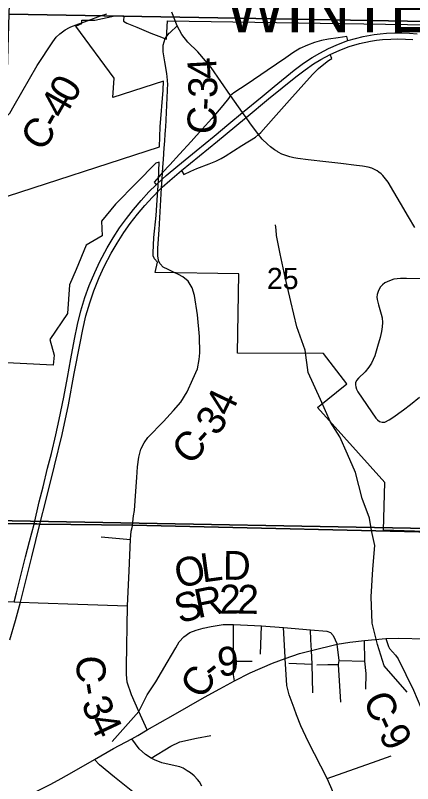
# Model space of a CAD drawing. Extents: x -19 to 40.8, y -1.8 to 26.1.
# Drawn here: x 5.34 to 6.121, y 15.443 to 16.956 of the extents above; entities that cross this region are included whole.
import ezdxf

# ---------------------------------------------------------------- set-up
doc = ezdxf.new("R2010")
doc.units = 0
for name, color, linetype in [('GM_X_City_Street', 7, 'Continuous'), ('GM_X_Corporation', 7, 'Continuous'), ('GM_X_County_Road', 7, 'Continuous'), ('GM_X_County_Road_Text', 7, 'Continuous'), ('GM_X_Major_River_Text', 7, 'Continuous'), ('GM_X_Rail_Line', 7, 'Continuous'), ('GM_X_Rail_Line_Text', 7, 'Continuous'), ('GM_X_Section', 7, 'Continuous'), ('GM_X_Section_Text', 7, 'Continuous'), ('GM_X_State_Route', 7, 'Continuous'), ('GM_X_Township_Road', 7, 'Continuous'), ('RW_P_Text', 7, 'Continuous')]:
    doc.layers.add(name, color=color, linetype=linetype)

msp = doc.modelspace()

# ---------------------------------------------------------------- linework, layer by layer
at = {"layer": 'GM_X_City_Street'}
for points in [[(5.2997, 16.5919), (5.6233, 16.6968), (5.6245, 16.736), (5.6304, 16.8084), (5.6314, 16.8263), (5.5318, 16.794), (5.5338, 16.8318), (5.4585, 16.9344), (5.4705, 16.9399), (5.4705, 16.9461), (5.4959, 16.9461), (5.5354, 16.9549), (5.5531, 16.9549), (5.5527, 16.944), (5.5593, 16.9404), (5.5785, 16.9328), (5.6064, 16.9208), (5.6217, 16.9151), (5.6372, 16.9092), (5.6373, 16.9102), (5.6389, 16.9451), (6.325, 16.9348)], [(6.2469, 15.9361), (6.0635, 15.9423), (6.0667, 16.0361), (5.9343, 16.1836), (5.9917, 16.2304), (5.946, 16.2903), (5.7766, 16.2907), (5.7795, 16.4467), (5.6145, 16.4497), (5.6191, 16.4696), (5.6133, 16.4766), (5.6111, 16.482), (5.6105, 16.4881), (5.6123, 16.5184), (5.6169, 16.5618), (5.6182, 16.5823), (5.6212, 16.6305), (5.6223, 16.6668), (5.6161, 16.665), (5.5781, 16.6258), (5.5365, 16.5843), (5.509, 16.5503), (5.5105, 16.5217), (5.4792, 16.503), (5.4591, 16.4556), (5.4462, 16.4254), (5.4423, 16.3689), (5.4076, 16.3176), (5.4159, 16.2869), (5.4141, 16.267), (5.2834, 16.2739)]]:
    msp.add_lwpolyline(points, dxfattribs=at)
at = {"layer": 'GM_X_Corporation'}
for p, q in [((5.644, 16.9219), (5.6582, 16.9352)), ((5.633, 16.7003), (5.6352, 16.7304))]:
    msp.add_line(p, q, dxfattribs=at)
for points in [[(5.483, 16.9459), (5.5075, 16.9546), (5.5195, 16.9585)], [(5.4465, 16.9319), (5.449, 16.9332), (5.4648, 16.9394), (5.483, 16.9459)], [(5.1684, 16.7259), (5.174, 16.7296), (5.1888, 16.7352), (5.2467, 16.7465), (5.2754, 16.7419), (5.3158, 16.7491), (5.329, 16.7629), (5.3375, 16.7783), (5.3827, 16.8572), (5.4132, 16.9039), (5.4201, 16.9126), (5.4273, 16.9192), (5.4375, 16.9273), (5.4465, 16.9319)], [(5.6391, 16.828), (5.638, 16.8411), (5.634, 16.8641), (5.6303, 16.8839), (5.6305, 16.8971), (5.6342, 16.9099), (5.6372, 16.9137), (5.6378, 16.9145)], [(5.6378, 16.9145), (5.6425, 16.9206), (5.6433, 16.9213), (5.644, 16.9219)], [(5.6352, 16.7304), (5.6355, 16.7354), (5.6395, 16.822), (5.6393, 16.825), (5.6391, 16.828)], [(5.6309, 16.6711), (5.6327, 16.6953), (5.633, 16.7003)], [(5.6223, 16.5336), (5.627, 16.6159), (5.6282, 16.633), (5.6292, 16.6462), (5.6305, 16.6653), (5.6309, 16.6711)], [(5.62, 16.4846), (5.6202, 16.4974), (5.6223, 16.5336)], [(5.6405, 16.4553), (5.6307, 16.4598), (5.6243, 16.4665), (5.6213, 16.4727), (5.621, 16.4747), (5.62, 16.4817), (5.62, 16.4846)], [(5.57, 15.9505), (5.5702, 15.9515), (5.5724, 15.9705), (5.5739, 15.9807), (5.5769, 16.0188), (5.5784, 16.0459), (5.5801, 16.067), (5.5825, 16.0862), (5.5866, 16.1019), (5.593, 16.1144), (5.6006, 16.1246), (5.6314, 16.156), (5.651, 16.1775), (5.665, 16.1943), (5.6779, 16.2142), (5.6887, 16.2396), (5.6977, 16.26), (5.7014, 16.2783), (5.7027, 16.2915), (5.702, 16.3234), (5.6977, 16.3664), (5.6923, 16.4045), (5.6878, 16.4195), (5.6796, 16.4327), (5.669, 16.4407), (5.6609, 16.4453), (5.6511, 16.4503), (5.6405, 16.4553)], [(5.5991, 15.5491), (5.5827, 15.585), (5.568, 15.6178), (5.5596, 15.6429), (5.5583, 15.658), (5.5583, 15.6736), (5.5604, 15.7932), (5.5633, 15.8624), (5.5663, 15.924), (5.5678, 15.94), (5.5694, 15.9476), (5.57, 15.9505)], [(5.5299, 15.5258), (5.5827, 15.585), (5.5993, 15.6178), (5.616, 15.6436), (5.6383, 15.6813), (5.6551, 15.7104), (5.6622, 15.7221), (5.6713, 15.7321), (5.683, 15.7406), (5.6956, 15.7453), (5.7094, 15.7492), (5.7247, 15.7524), (5.7484, 15.7564), (5.7691, 15.7566), (5.8238, 15.754), (5.8671, 15.7502), (5.9204, 15.7461), (5.9521, 15.7431), (5.9596, 15.7405), (5.9649, 15.7349), (5.9727, 15.7177)], [(5.5991, 15.5491), (5.6501, 15.5782), (5.7116, 15.6132), (5.7421, 15.6295), (5.771, 15.6458), (5.8017, 15.6613), (5.8457, 15.68), (5.8707, 15.6893), (5.8985, 15.6992), (5.9223, 15.7051), (5.9727, 15.7177)], [(5.9727, 15.7177), (5.9977, 15.7217), (6.0267, 15.7252), (6.0683, 15.7291)], [(6.0683, 15.7291), (6.093, 15.7296), (6.1466, 15.7285), (6.1833, 15.7258), (6.2138, 15.7217), (6.2422, 15.7176)], [(6.0683, 15.7291), (6.0733, 15.7128), (6.0759, 15.7091), (6.0816, 15.7026), (6.0877, 15.6959), (6.0929, 15.689), (6.1229, 15.6269), (6.1373, 15.5931), (6.1466, 15.5737), (6.1562, 15.5575), (6.1621, 15.5501), (6.1685, 15.5443), (6.1791, 15.5394), (6.1851, 15.5381), (6.1921, 15.5378), (6.1997, 15.5386), (6.2062, 15.5414), (6.2224, 15.5504), (6.2431, 15.5632), (6.2778, 15.5852), (6.2888, 15.5919)], [(5.5689, 15.531), (5.5808, 15.5379), (5.5991, 15.5491)], [(5.4955, 15.4905), (5.5326, 15.512), (5.5689, 15.531)], [(5.352, 15.415), (5.371, 15.4233), (5.3897, 15.4319), (5.4095, 15.4421), (5.4296, 15.453), (5.4506, 15.4652), (5.4955, 15.4905)], [(5.5777, 15.4216), (5.535, 15.4561), (5.5055, 15.4803), (5.4955, 15.4905)]]:
    msp.add_lwpolyline(points, dxfattribs=at)
at = {"layer": 'GM_X_County_Road'}
for points in [[(5.9936, 16.906), (5.9919, 16.9139), (5.9744, 16.9116), (5.9554, 16.9088), (5.9419, 16.9061), (5.9281, 16.9023), (5.9144, 16.8973), (5.8994, 16.8903), (5.8852, 16.8817), (5.8715, 16.8721), (5.835, 16.8475), (5.7958, 16.8204), (5.7693, 16.8031), (5.7631, 16.7982)], [(5.8179, 16.7211), (5.8225, 16.7252), (5.8472, 16.7533), (5.8791, 16.7887), (5.924, 16.8391), (5.9361, 16.8511), (5.9464, 16.8599), (5.9557, 16.8667), (5.9621, 16.8711), (5.9588, 16.8787)], [(5.7631, 16.7982), (5.7588, 16.792), (5.7479, 16.7783), (5.7264, 16.7529), (5.7074, 16.7314), (5.6858, 16.7075), (5.6627, 16.6824), (5.6436, 16.6616), (5.6292, 16.6462), (5.6217, 16.6377)], [(5.6663, 16.65), (5.6709, 16.6424), (5.6847, 16.6491), (5.697, 16.6541), (5.7212, 16.6634), (5.7339, 16.6685), (5.7447, 16.6737), (5.7527, 16.6786), (5.7851, 16.6994), (5.8118, 16.716), (5.8179, 16.7211)], [(5.6217, 16.6377), (5.6128, 16.6276), (5.6164, 16.6221)]]:
    msp.add_lwpolyline(points, dxfattribs=at)
at = {"layer": 'GM_X_Rail_Line'}
for points in [[(5.7631, 16.7982), (5.7251, 16.8529), (5.6987, 16.8841), (5.6791, 16.903), (5.6671, 16.918), (5.6582, 16.9352), (5.6478, 16.9623)], [(5.8012, 16.7441), (5.7934, 16.7549), (5.7867, 16.7645), (5.7631, 16.7982)], [(5.8551, 16.6876), (5.8492, 16.6912), (5.8417, 16.6967), (5.8354, 16.7019), (5.8251, 16.7117), (5.8179, 16.7211), (5.8012, 16.7441)], [(6.1251, 16.5378), (6.113, 16.559), (6.0974, 16.5857), (6.0843, 16.608), (6.0728, 16.6272), (6.068, 16.634), (6.0623, 16.6407), (6.059, 16.644), (6.0548, 16.6472), (6.0512, 16.6498), (6.0473, 16.6519), (6.0406, 16.6546), (6.0337, 16.6567), (6.0223, 16.6587), (6.0108, 16.6602), (5.9797, 16.6639), (5.9502, 16.6671), (5.9155, 16.671), (5.8955, 16.6737), (5.8872, 16.6753), (5.8793, 16.6774), (5.8718, 16.6798), (5.8641, 16.6827), (5.8568, 16.6866), (5.8551, 16.6876)]]:
    msp.add_lwpolyline(points, dxfattribs=at)
at = {"layer": 'GM_X_Rail_Line_Text'}
msp.add_lwpolyline([(6.1385, 16.437), (6.1089, 16.4378), (6.097, 16.4376), (6.0844, 16.4361), (6.0754, 16.4334), (6.0664, 16.429), (6.062, 16.4255), (6.0576, 16.421), (6.054, 16.414), (6.0512, 16.4062), (6.0509, 16.4012), (6.0512, 16.3964), (6.054, 16.3859), (6.059, 16.3677), (6.0609, 16.3599), (6.0616, 16.351), (6.061, 16.3428), (6.0599, 16.3336), (6.0571, 16.3216), (6.0522, 16.3041), (6.0466, 16.2852), (6.0403, 16.2712), (6.0351, 16.2632), (6.028, 16.2539), (6.0145, 16.2416), (6.0108, 16.2371), (6.0088, 16.232), (6.0085, 16.2284), (6.0093, 16.2242), (6.0109, 16.2199), (6.0134, 16.2145), (6.0487, 16.1624), (6.052, 16.1591), (6.0559, 16.1563), (6.061, 16.1548), (6.0663, 16.155), (6.0748, 16.1591), (6.0823, 16.164), (6.1034, 16.1791), (6.1168, 16.1895), (6.1345, 16.2043)], dxfattribs=at)
at = {"layer": 'GM_X_Section'}
msp.add_lwpolyline([(6.1102, 15.6234), (6.0651, 15.6748), (6.0523, 15.7168), (6.0413, 15.7588), (6.0396, 15.8112), (6.0428, 15.8652), (6.0469, 15.9117), (6.0399, 15.9416), (6.0365, 15.9658), (6.0218, 16.0044), (6.0088, 16.0554), (5.993, 16.092), (5.9777, 16.1256), (5.9598, 16.155), (5.9397, 16.1995), (5.9157, 16.2523), (5.91, 16.2966), (5.8933, 16.3423), (5.8818, 16.3923), (5.8707, 16.44), (5.8605, 16.4862), (5.8534, 16.5222), (5.8524, 16.5332), (5.8511, 16.5434)], dxfattribs=at)
at = {"layer": 'GM_X_State_Route'}
for p, q in [((5.5086, 15.929), (5.5663, 15.924)), ((5.8217, 15.6981), (5.8238, 15.754)), ((5.8705, 15.6922), (5.8671, 15.7502)), ((5.7687, 15.684), (5.8057, 15.6844)), ((5.8779, 15.6802), (5.9234, 15.6784)), ((5.9327, 15.6773), (5.9541, 15.6776)), ((5.9541, 15.6776), (5.9755, 15.6779)), ((5.9763, 15.6858), (6.0272, 15.6841))]:
    msp.add_line(p, q, dxfattribs=at)
for points in [[(4.3769, 16.7589), (4.3704, 16.384), (4.3644, 15.9666), (5.2419, 15.956), (5.3769, 15.9544), (5.3823, 15.9544), (5.3878, 15.9543), (5.57, 15.952), (6.2458, 15.936), (6.5861, 15.9329), (6.6409, 15.9314), (6.7023, 15.9297), (6.805, 15.9268), (6.9672, 15.9223), (6.993, 15.9217), (6.9993, 15.9207), (7.1288, 15.9169)], [(7.1288, 15.9169), (6.9993, 15.9207), (6.993, 15.9217), (6.9672, 15.9223), (6.805, 15.9268), (6.7023, 15.9297), (6.6409, 15.9314), (6.5861, 15.9329), (6.2458, 15.936), (5.57, 15.952), (5.3878, 15.9543), (5.3823, 15.9544), (5.3769, 15.9544), (5.2419, 15.956), (4.3644, 15.9666), (4.3628, 15.868), (4.3494, 15.3211)], [(5.229, 15.8048), (5.2377, 15.8045), (5.3375, 15.8009), (5.3497, 15.8003), (5.3849, 15.7991)], [(5.3849, 15.7991), (5.463, 15.7964), (5.5604, 15.7932)], [(5.771, 15.6458), (5.7685, 15.6572), (5.7687, 15.684), (5.7691, 15.7566)], [(5.9249, 15.6219), (5.9234, 15.6784), (5.9223, 15.7051), (5.9208, 15.7261), (5.9204, 15.7461)], [(5.9799, 15.6034), (5.9755, 15.6779), (5.9763, 15.6858), (5.9727, 15.7177)], [(6.0293, 15.629), (6.0298, 15.6599), (6.0272, 15.6841), (6.0267, 15.7252)], [(5.9697, 15.3507), (5.968, 15.4103), (5.9657, 15.4242), (5.9604, 15.437), (5.9533, 15.4531), (5.9159, 15.5259), (5.9009, 15.5571), (5.8924, 15.5788), (5.8879, 15.5918), (5.878, 15.6177), (5.8737, 15.6361), (5.8707, 15.6893), (5.8705, 15.6922)], [(5.607, 15.493), (5.6456, 15.5168), (5.6632, 15.5256), (5.6962, 15.5327), (5.724, 15.5377)], [(5.7066, 15.4383), (5.7017, 15.4465), (5.6977, 15.4515), (5.6916, 15.4584), (5.6844, 15.4641), (5.6777, 15.4686), (5.6701, 15.4736), (5.663, 15.4762), (5.642, 15.4808), (5.6278, 15.4841), (5.6134, 15.4897), (5.607, 15.493), (5.5956, 15.5005), (5.583, 15.5114), (5.5689, 15.531)], [(5.9533, 15.4531), (6.0512, 15.4883), (6.0788, 15.4978)]]:
    msp.add_lwpolyline(points, dxfattribs=at)
at = {"layer": 'GM_X_Township_Road'}
for points in [[(5.9936, 16.906), (6.0239, 16.9142), (6.0452, 16.918), (6.0572, 16.9196), (6.0696, 16.9207), (6.086, 16.9213), (6.0997, 16.9214), (6.115, 16.9206), (6.1299, 16.9191)], [(5.6164, 16.6221), (5.6282, 16.633), (5.6365, 16.6406), (5.6594, 16.6598), (5.6953, 16.6892), (5.7306, 16.7182), (5.7599, 16.7425), (5.7867, 16.7645), (5.8249, 16.796), (5.849, 16.8159), (5.8883, 16.8479), (5.9067, 16.8617), (5.9236, 16.873), (5.9383, 16.8815), (5.9559, 16.8907), (5.9751, 16.899), (5.9936, 16.906)], [(5.7903, 16.7523), (5.7934, 16.7549), (5.8379, 16.7912), (5.8911, 16.8348), (5.9095, 16.8488), (5.9264, 16.8605), (5.9407, 16.8691), (5.9588, 16.8787), (5.9777, 16.8872), (5.9962, 16.8942), (6.0167, 16.9002), (6.0385, 16.9048), (6.0498, 16.9068), (6.0619, 16.908), (6.078, 16.9091), (6.0916, 16.9094), (6.1069, 16.9091), (6.1214, 16.908)], [(5.6286, 16.6172), (5.6438, 16.6306), (5.6663, 16.65), (5.7372, 16.7082), (5.7903, 16.7523)], [(5.3288, 15.7264), (5.3403, 15.7641), (5.3497, 15.8003), (5.3591, 15.8373), (5.3723, 15.8897), (5.388, 15.9537), (5.4004, 16.0027), (5.4168, 16.0689), (5.4316, 16.1302), (5.4441, 16.189), (5.4557, 16.2507), (5.4671, 16.3105), (5.4722, 16.3374), (5.4786, 16.3641), (5.4862, 16.39), (5.4942, 16.4137), (5.5045, 16.4396), (5.5145, 16.4611), (5.5281, 16.4877), (5.5397, 16.5074), (5.5532, 16.5281), (5.5657, 16.546), (5.5801, 16.5643), (5.5942, 16.5815), (5.6095, 16.598), (5.6232, 16.612), (5.627, 16.6159), (5.6286, 16.6172)], [(5.3375, 15.8009), (5.3421, 15.8189), (5.3493, 15.8476), (5.3599, 15.8899), (5.3673, 15.9198), (5.3771, 15.9539), (5.3868, 15.9978), (5.3942, 16.0272), (5.4033, 16.0641), (5.4106, 16.0934), (5.4193, 16.1299), (5.4258, 16.1598), (5.4349, 16.2037), (5.4421, 16.2426), (5.4489, 16.2797), (5.456, 16.3181), (5.4621, 16.3469), (5.4687, 16.3739), (5.4767, 16.4002), (5.4852, 16.4238), (5.4959, 16.4498), (5.5058, 16.4709), (5.5202, 16.4978), (5.532, 16.5177), (5.5448, 16.5374), (5.5583, 16.556), (5.5719, 16.5736), (5.587, 16.5913), (5.6026, 16.608), (5.6164, 16.6221)]]:
    msp.add_lwpolyline(points, dxfattribs=at)
at = {"layer": 'RW_P_Text'}
msp.add_lwpolyline([(5.3496, 17.5837), (5.3629, 17.962), (6.3691, 17.9545), (6.3345, 16.9403), (5.3277, 16.9579), (5.3482, 17.5425)], dxfattribs=at)
for points in [[(6.3345, 16.9403), (6.2953, 15.9429), (5.2973, 15.9612), (5.3277, 16.9579)], [(5.2973, 15.9612), (6.2953, 15.9429), (6.2831, 14.8757), (5.2615, 14.8764), (5.2848, 15.9609)]]:
    msp.add_lwpolyline(points, close=True, dxfattribs=at)

# ---------------------------------------------------------------- texts
at = {"layer": 'GM_X_County_Road_Text'}
for s, rotation, p in [('4', 93.1496, (5.7367, 16.8318)), ('0', 59.6877, (5.4519, 16.7795)), ('3', 89.8258, (5.7367, 16.7932)), ('4', 60.2635, (5.4346, 16.7492)), ('-', 88.1821, (5.7359, 16.7681)), ('-', 60.6035, (5.4232, 16.729)), ('C', 87.5989, (5.7339, 16.7208)), ('C', 53.4369, (5.3912, 16.685)), ('4', 64.4482, (5.7619, 16.1632)), ('3', 54.431, (5.7361, 16.1254)), ('C', 46.8659, (5.6833, 16.0677)), ('-', 47.8984, (5.716, 16.1026)), ('D', 359.4427, (5.7477, 15.8446)), ('O', 14.7404, (5.6613, 15.8266)), ('L', 7.7725, (5.7078, 15.839)), ('S', 17.6086, (5.6634, 15.7574)), ('R', 11.4768, (5.6984, 15.7686)), ('2', 0.8327, (5.7414, 15.7776)), ('2', 358.8655, (5.7758, 15.7781)), ('9', 4.6145, (5.7392, 15.6543)), ('C', 269.356, (5.4608, 15.6957)), ('C', 60.0116, (5.7099, 15.607)), ('-', 39.0375, (5.7295, 15.643)), ('-', 278.9503, (5.461, 15.6387)), ('3', 292.3293, (5.4686, 15.6017)), ('C', 293.1402, (6.0227, 15.6098)), ('4', 295.143, (5.4831, 15.5665)), ('-', 294.5129, (6.0417, 15.5655)), ('9', 297.9513, (6.053, 15.5409))]:
    msp.add_text(s, height=0.0568, rotation=rotation, dxfattribs=at).set_placement(p)
at = {"layer": 'GM_X_Major_River_Text'}
msp.add_text('WINTERSVILLE', height=0.094697, rotation=0, dxfattribs=at).set_placement((5.7523, 16.9225))
at = {"layer": 'GM_X_Section_Text'}
msp.add_text('25', height=0.04186, rotation=0, dxfattribs=at).set_placement((5.8344, 16.4168))

doc.saveas('drawing.dxf')
